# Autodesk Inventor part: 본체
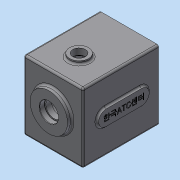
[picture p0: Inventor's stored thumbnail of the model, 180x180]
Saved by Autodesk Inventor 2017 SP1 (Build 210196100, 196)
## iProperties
Created: 2016-02
Part Number: 본체
Material: 알루미늄 6061
Document SubType Name: Modeling
Designer: mduedu
Density: 2.7 g/cm^3
Mass: 1511.55 g
Surface Area: 1073.15 cm^2
Volume: 559.832 cm^3
Appearance: 기본값
Author: mduedu
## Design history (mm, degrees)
sketch "스케치1"
  geometry: L1 (-47, -47)-(47, -47); L2 (47, -47)-(47, 63); L3 (47, 63)-(-47, 63); L4 (-47, 63)-(-47, -47); 2 further points
  constraints: 8 end point, 2 parallel, 1 horizontal, 1 midpoint, 1 perpendicular, 1 vertical alignment
  dimensions: "d0" = 94 distance of L2.end L3.end; "d155" = 110 distance of L1.end L2.end; "d156" = 47 distance from line of L1 point (0, 0)
extrude "돌출1" new body sketch "스케치1" distance "d2" = 120; taper "d3" = 0 deg
sketch "스케치3"
  geometry: L1 (47, -47)-(-47, -47) reference; L2 (47, 63)-(47, -47) reference; L3 (-47, 63)-(47, 63) reference; L4 (-47, -47)-(-47, 63) reference; L5 (37, 53)-(37, -37); L6 (37, -37)-(-37, -37); L7 (-37, -37)-(-37, 53); L8 (-37, 53)-(37, 53); 1 further point
  constraints: 8 end point, 3 other
  dimensions: "d226" = 10 distance between parallel lines of L8 L3
extrude "돌출3" cut sketch "스케치3" distance "d11" = 110; taper "d12" = 0 deg
sketch "스케치4"
  geometry: C1 r 21 at (0, 11); 1 further point
  constraints: 1 centre point, 1 vertical alignment
  dimensions: "d13" = 21 radius of C1; "d227" = 11 distance of point (0, 0) C1.centre
extrude "돌출4" join sketch "스케치4" distance "d16" = 7; taper "d17" = 0 deg
sketch "스케치5"
  geometry: C1 r 15 at (0, -20); 1 further point
  constraints: 1 centre point, 1 vertical alignment
  dimensions: "d18" = 15 radius of C1; "d20" = 20 distance of point (0, 0) C1.centre
extrude "돌출5" join sketch "스케치5" distance "d21" = 7; taper "d22" = 0 deg
sketch "스케치6"
  geometry: C1 r 30 at (0, 11); A1 r 21 centre (0, 11) between (8.978, -7.984) and (-8.978, -7.984) reference; 1 further point
  constraints: 1 centre point, 1 coincident
  dimensions: "d228" = 60 diameter of C1
extrude "돌출6" join sketch "스케치6" distance "d25" = 7; taper "d26" = -3 deg
hole "구멍1" diameter "d29" = 30; stored, may be unused: countersink angle "d33" = 90 deg, drill point angle "d35" = 0 deg; dims "d30" = 6, "d31" = 4, "d32" = 2, "d34" = 7, "d269" = 10, "d270" = 10
hole "구멍2" diameter "d38" = 22; stored, may be unused: countersink angle "d42" = 90 deg, drill point angle "d44" = 0 deg; dims "d36" = 10, "d37" = 10, "d39" = 6, "d40" = 4, "d41" = 2, "d43" = 7
hole "구멍3" diameter "d47" = 19; stored, may be unused: countersink angle "d51" = 90 deg, drill point angle "d53" = 0 deg; dims "d45" = 10, "d46" = 10, "d48" = 6, "d49" = 4, "d50" = 2, "d52" = 1
hole "구멍4" diameter "d56" = 30; stored, may be unused: countersink angle "d60" = 90 deg, drill point angle "d62" = 0 deg; dims "d57" = 6, "d58" = 4, "d59" = 2, "d61" = 8.3, "d271" = 10, "d272" = 10
hole "구멍5" diameter "d65" = 26; stored, may be unused: countersink angle "d69" = 90 deg, drill point angle "d71" = 0 deg; dims "d66" = 6, "d67" = 4, "d68" = 2, "d70" = 8, "d267" = 10, "d268" = 10
fillet "모깎기2" dims "d73" = 0.3
fillet "모깎기3" dims "d74" = 2
chamfer "모따기1" distance "d75" = 1; stored, may be unused: second distance "d76" = 2, angle "d77" = 45 deg
fillet "모깎기4" dims "d78" = 3
fillet "모깎기23" dims "d240" = 1
fillet "모깎기20" dims "d229" = 3
sketch "스케치23"
  geometry: L1 (-37, 53)-(37, 53) reference; L2 (37, 53)-(37, -37) reference; L3 (37, -37)-(-37, -37) reference; L4 (-37, -37)-(-37, 53) reference; L5 (44, -47)-(-44, -47) reference; L6 (47, 60)-(47, -44) reference; L7 (-44, 63)-(44, 63) reference; L8 (-47, -44)-(-47, 60) reference; C1 r 10 at (-37, 53); C2 r 10 at (37, 53); C3 r 10 at (-37, -37); C4 r 10 at (37, -37); A1 r 3 centre (-44, -44) between (-47, -44) and (-44, -47) reference; A2 r 3 centre (44, -44) between (44, -47) and (47, -44) reference; A3 r 3 centre (44, 60) between (47, 60) and (44, 63) reference; A4 r 3 centre (-44, 60) between (-44, 63) and (-47, 60) reference; 1 further point
  constraints: 4 centre point, 4 coincident, 3 equal radius
  dimensions: "d230" = 20 diameter of C1
extrude "돌출22" join sketch "스케치23" stored distance "d235" = 10; taper "d236" = 0 deg
fillet "모깎기21" dims "d237" = 3
node "작업 평면1"
fillet "모깎기22" dims "d239" = 1
sketch "스케치12"
  geometry: A1 r 10 centre (-37, 53) between (-34.692, 43.27) and (-27.27, 50.692) reference; A2 r 10 centre (37, 53) between (27.27, 50.692) and (34.692, 43.27) reference; A3 r 10 centre (37, -37) between (34.692, -27.27) and (27.27, -34.692) reference; A4 r 10 centre (-37, -37) between (-27.27, -34.692) and (-34.692, -27.27) reference; 5 further points
  constraints: 4 coincident
hole "구멍6" sketch "스케치12" at (-37, 53), (37, 53), (37, -37), (-37, -37) diameter "d122" = 3.242; stored, may be unused: countersink angle "d126" = 90 deg, drill point angle "d128" = 120 deg; dims "d123" = 7, "d124" = 4, "d125" = 2, "d127" = 9
sketch "스케치20"
  geometry: L1 (44, 0)-(-44, 0) reference; L2 (44, -120)-(-44, -120) reference; L3 (0, 0)-(0, -120); L4 (-44, -120)-(-44, 0) reference; L5 (44, 0)-(44, -120) reference; C1 r 10 at (0, -79)
  constraints: 2 end point, 1 centre point, 1 midpoint, 1 point on line
  dimensions: "d189" = 20 diameter of C1; "d190" = 41 distance from line of C1.centre L2
extrude "돌출19" cut sketch "스케치20" stored distance "d191" = 10; taper "d192" = 0 deg
sketch "스케치18"
  geometry: C1 r 15 at (0, -79); C2 r 10 at (0, -79) reference; 1 further point
  constraints: 1 centre point, 1 concentric
  dimensions: "d174" = 30 diameter of C1
extrude "돌출17" join sketch "스케치18" distance "d175" = 5; taper "d176" = 0 deg
fillet "모깎기16" dims "d177" = 3
sketch "스케치19"
  geometry: C1 r 15 at (24.351, 79); C2 r 10 at (24.351, 79) reference; 1 further point
  constraints: 1 centre point, 1 concentric
  dimensions: "d178" = 30 diameter of C1
extrude "돌출18" cut sketch "스케치19" distance "d181" = 5; taper "d182" = 0 deg
chamfer "모따기5" distance "d183" = 1; stored, may be unused: second distance "d184" = 2, angle "d185" = 45 deg
fillet "모깎기24" dims "d242" = 3, "d243" = 3
sketch "스케치24"
  geometry: L1 (-86, 64)-(-30, 64); L2 (-30, 64)-(-30, 40); L3 (-30, 40)-(-86, 40); L4 (-86, 40)-(-86, 64); L5 (0, 0)-(0, 104) reference; L6 (-86, 52)-(-30, 52); L7 (-58, 64)-(-58, 40); A1 r 12 centre (-86, 52) between (-86, 40) and (-86, 64); A2 r 12 centre (-30, 52) between (-30, 64) and (-30, 40); A3 r 12 centre (-30, 52) between (-30, 40) and (-30, 64); A4 r 12 centre (-86, 52) between (-86, 64) and (-86, 40); 2 further points
  constraints: 12 end point, 8 point on circle, 5 midpoint, 4 centre point, 2 parallel, 2 perpendicular, 1 horizontal, 1 horizontal alignment
  dimensions: "d244" = 58 distance between parallel lines of L7 L5; "d245" = 80 dimension on A2 A1; "d246" = 24 distance between parallel lines of L3 L1
extrude "돌출23" join sketch "스케치24" distance "d247" = 3; taper "d248" = 0 deg
fillet "모깎기25" dims "d249" = 3
sketch "스케치25"
  geometry: L1 (-30, 64)-(-86, 64) reference; L2 (-86, 40)-(-30, 40) reference; A1 r 12 centre (-86, 52) between (-86, 64) and (-86, 40) reference; A2 r 12 centre (-30, 52) between (-30, 40) and (-30, 64) reference; 3 further points
  constraints: 1 horizontal alignment, 1 midpoint, 1 vertical alignment, 1 other
feature "엠보싱3" sketch "스케치25" dims "d32" = 2, "d250" = 0.5, "d251" = 0
sketch "스케치26"
  geometry: L1 (14.367, 127)-(73.633, 127) reference; L2 (0, 0)-(88, 0) reference; L3 (88, 120)-(0, 120) reference; 5 further points
  constraints: 3 vertical alignment, 2 midpoint
  dimensions: "d252" = 35 distance from line of point (44, 35) L2; "d253" = 35 distance from line of point (44, 85) L3; "d254" = 50 distance of point (44, 35) point (44, 85) (derived)
hole "구멍8" sketch "스케치26" at (44, 85), (44, 35) diameter "d255" = 6.647; stored, may be unused: countersink angle "d259" = 90 deg, drill point angle "d261" = 118 deg; dims "d256" = 6, "d257" = 4, "d258" = 2, "d260" = 8
chamfer "모따기7" distance "d262" = 0.8; stored, may be unused: second distance "d263" = 2, angle "d264" = 30 deg
node "솔리드1"
node "투영된 루프1"
node "투영된 루프4"
node "투영된 루프5"
node "투영된 루프6"
